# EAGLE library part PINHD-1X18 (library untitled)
PIN HEADER
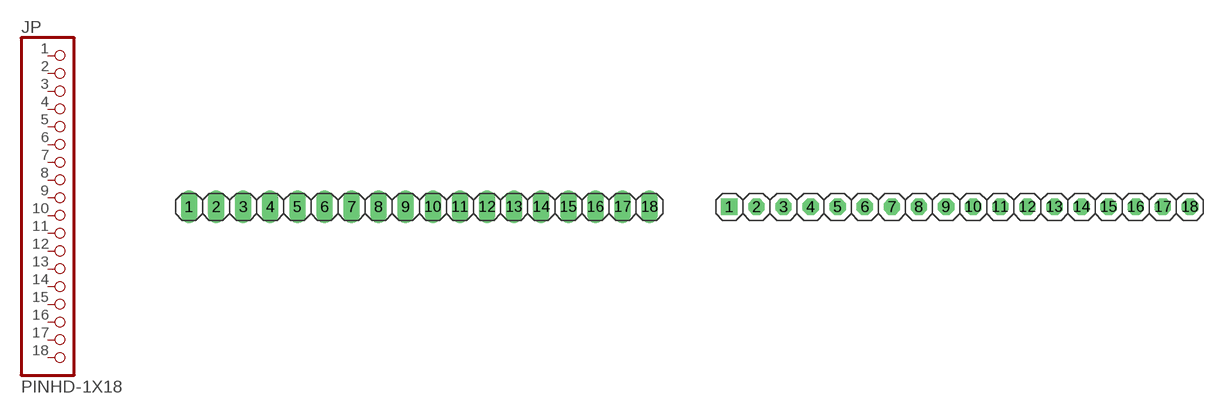
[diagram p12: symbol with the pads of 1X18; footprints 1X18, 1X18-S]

Designator prefix JP

## PINHD-1X18_2.54  [1X18]
1  1  pas
2  2  pas
3  3  pas
4  4  pas
5  5  pas
6  6  pas
7  7  pas
8  8  pas
9  9  pas
10  10  pas
11  11  pas
12  12  pas
13  13  pas
14  14  pas
15  15  pas
16  16  pas
17  17  pas
18  18  pas

## PINHD-1X18_2.54-S  [1X18-S]
Pads as for 1X18

## PINHD-1X18_2.54-90°  [1X18/90]
Pads as for 1X18

## PINHD-1X18_2.54-90°-S  [1X18/90-S]
Pads as for 1X18

## PINHD-1X18_2.00  [1X18M]
Pads as for 1X18

## PINHD-1X18_2.54-SMD  [1X18SMD]
Pads as for 1X18

## PINHD-1X18_2.54-SMD-90°  [1X18SMD/90]
Pads as for 1X18

## Footprint 1X18 (pad centres in mm)
PIN HEADER - 2.54
drill 1.016 long: 1 -21.59,0; 2 -19.05,0; 3 -16.51,0; 4 -13.97,0; 5 -11.43,0; 6 -8.89,0; 7 -6.35,0; 8 -3.81,0; 9 -1.27,0; 10 1.27,0; 11 3.81,0; 12 6.35,0; 13 8.89,0; 14 11.43,0; 15 13.97,0; 16 16.51,0; 17 19.05,0; 18 21.59,0

## Footprint 1X18-S (pad centres in mm)
PIN HEADER - 2.54
drill 1.016 square: 1 -21.59,0
drill 1.016 octagon: 2 -19.05,0; 3 -16.51,0; 4 -13.97,0; 5 -11.43,0; 6 -8.89,0; 7 -6.35,0; 8 -3.81,0; 9 -1.27,0; 10 1.27,0; 11 3.81,0; 12 6.35,0; 13 8.89,0; 14 11.43,0; 15 13.97,0; 16 16.51,0; 17 19.05,0; 18 21.59,0

## Footprint 1X18/90 (pad centres in mm)
PIN HEADER - 2.54 90°
drill 1.016 long: 1 -21.59,-3.81; 2 -19.05,-3.81; 3 -16.51,-3.81; 4 -13.97,-3.81; 5 -11.43,-3.81; 6 -8.89,-3.81; 7 -6.35,-3.81; 8 -3.81,-3.81; 9 -1.27,-3.81; 10 1.27,-3.81; 11 3.81,-3.81; 12 6.35,-3.81; 13 8.89,-3.81; 14 11.43,-3.81; 15 13.97,-3.81; 16 16.51,-3.81; 17 19.05,-3.81; 18 21.59,-3.81

## Footprint 1X18/90-S (pad centres in mm)
PIN HEADER - 2.54 90°
drill 1.016 square: 1 -21.59,-3.81
drill 1.016 octagon: 2 -19.05,-3.81; 3 -16.51,-3.81; 4 -13.97,-3.81; 5 -11.43,-3.81; 6 -8.89,-3.81; 7 -6.35,-3.81; 8 -3.81,-3.81; 9 -1.27,-3.81; 10 1.27,-3.81; 11 3.81,-3.81; 12 6.35,-3.81; 13 8.89,-3.81; 14 11.43,-3.81; 15 13.97,-3.81; 16 16.51,-3.81; 17 19.05,-3.81; 18 21.59,-3.81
